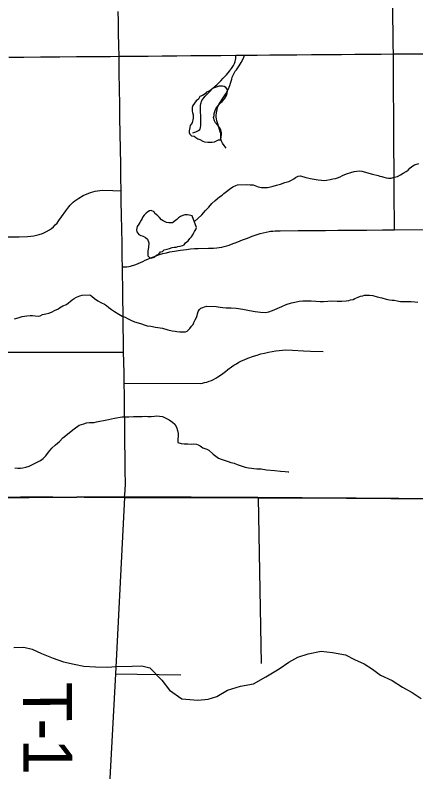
# Model space of a CAD drawing. Extents: x 0 to 34, y 0 to 22.
# Drawn here: x 3.526 to 3.992, y 15.034 to 15.914 of the extents above; entities that cross this region are included whole.
import ezdxf

# ---------------------------------------------------------------- set-up
doc = ezdxf.new("R2010")
doc.units = 0
for name, color, linetype in [('GM_X_City_Street', 7, 'Continuous'), ('GM_X_County_Road', 7, 'Continuous'), ('GM_X_County_Text', 7, 'Continuous'), ('GM_X_Minor_Lake', 7, 'Continuous'), ('GM_X_Minor_River', 7, 'Continuous'), ('GM_X_Township_Road', 7, 'Continuous'), ('GM_X_Township_Road_Text', 7, 'Continuous'), ('SH_Cut_Line', 7, 'Continuous')]:
    doc.layers.add(name, color=color, linetype=linetype)

msp = doc.modelspace()

# ---------------------------------------------------------------- linework, layer by layer
at = {"layer": 'GM_X_City_Street'}
msp.add_line((3.33353, 15.52258), (3.65196, 15.52258), dxfattribs=at)
for points in [[(3.65298, 15.35362), (3.65372, 15.36143), (3.65397, 15.36952), (3.6538, 15.38426), (3.65362, 15.39953), (3.6534, 15.41789), (3.65317, 15.43737), (3.65296, 15.45612), (3.65276, 15.47253), (3.6526, 15.48625), (3.6524, 15.49744), (3.65216, 15.51118), (3.65196, 15.52258), (3.65175, 15.53697), (3.65155, 15.55073), (3.6513, 15.56788), (3.65105, 15.58457), (3.65083, 15.59941), (3.65066, 15.61118), (3.65051, 15.6216), (3.65033, 15.63231), (3.65004, 15.64917), (3.64977, 15.66545), (3.6495, 15.68163), (3.64923, 15.69742), (3.64902, 15.70986), (3.64877, 15.72556), (3.64852, 15.74151), (3.64826, 15.75803), (3.64796, 15.7771), (3.64769, 15.79428), (3.64743, 15.81063), (3.64716, 15.8279), (3.64685, 15.84788), (3.64656, 15.86637), (3.64635, 15.87915), (3.64611, 15.89326), (3.64588, 15.90714), (3.64569, 15.91854)], [(3.96667, 15.66466), (3.96657, 15.68081), (3.96649, 15.69426), (3.96639, 15.71042), (3.9663, 15.72481), (3.96621, 15.73903), (3.9661, 15.75638), (3.96598, 15.77525), (3.96588, 15.79083), (3.9658, 15.80394), (3.96569, 15.82096), (3.96559, 15.83644), (3.96549, 15.85328), (3.96539, 15.86912), (3.96528, 15.87961), (3.9651, 15.8956), (3.96495, 15.90999), (3.96482, 15.92226)], [(3.73221, 15.77748), (3.73572, 15.77869), (3.73741, 15.77939), (3.73894, 15.78022), (3.74038, 15.78131), (3.74104, 15.78234), (3.74138, 15.78336), (3.74172, 15.7864), (3.7418, 15.79001), (3.74153, 15.79695), (3.74128, 15.8022), (3.74121, 15.80584), (3.74145, 15.80939), (3.74161, 15.81121), (3.74189, 15.81238), (3.74233, 15.8138), (3.74293, 15.81519), (3.7438, 15.81647), (3.74499, 15.81817), (3.74666, 15.82007), (3.74862, 15.82218), (3.75154, 15.82525), (3.75566, 15.82931), (3.76047, 15.83369), (3.76474, 15.8377), (3.76776, 15.84096), (3.76967, 15.84286), (3.7714, 15.84485), (3.77511, 15.8492), (3.77739, 15.85224), (3.77965, 15.85577), (3.7809, 15.85807), (3.78161, 15.8604), (3.78214, 15.86397), (3.78239, 15.86764)], [(3.77117, 15.75959), (3.76867, 15.76286), (3.76688, 15.76554), (3.76561, 15.76782), (3.76516, 15.76893), (3.76479, 15.7702), (3.76472, 15.77183), (3.76487, 15.77361), (3.76494, 15.77517), (3.76479, 15.77681), (3.76429, 15.77872), (3.76267, 15.78389), (3.76085, 15.78904), (3.76026, 15.79145), (3.75989, 15.7936), (3.75966, 15.79561), (3.75959, 15.79747), (3.75989, 15.80066), (3.76055, 15.80445), (3.76119, 15.80675), (3.76211, 15.80937), (3.76299, 15.81111), (3.76401, 15.81262), (3.76687, 15.81683), (3.77073, 15.82291), (3.77281, 15.82638), (3.77384, 15.8284), (3.77475, 15.8306), (3.77537, 15.83238), (3.77659, 15.83642), (3.7775, 15.83989), (3.77824, 15.84227), (3.77921, 15.84464), (3.78047, 15.84695), (3.78173, 15.84895), (3.78292, 15.85051), (3.78612, 15.85542), (3.78856, 15.85928), (3.7905, 15.8627), (3.79168, 15.86543), (3.79229, 15.8677)], [(3.51197, 15.65638), (3.53055, 15.65654), (3.54028, 15.65675), (3.54403, 15.65712), (3.54775, 15.65769), (3.55072, 15.65831), (3.55364, 15.65913), (3.55771, 15.66056), (3.56009, 15.66152), (3.56239, 15.66264), (3.56572, 15.66458), (3.5681, 15.66634), (3.57036, 15.66825), (3.5725, 15.67029), (3.57452, 15.67247), (3.57659, 15.67533), (3.5797, 15.67959), (3.58474, 15.68681), (3.58808, 15.69125), (3.58966, 15.69317), (3.59139, 15.69498), (3.59322, 15.69666), (3.59518, 15.69822), (3.59976, 15.70132), (3.60506, 15.70457), (3.60778, 15.70588), (3.61057, 15.70705), (3.61343, 15.70807), (3.61633, 15.70892), (3.61896, 15.7096), (3.62163, 15.71013), (3.62432, 15.71049), (3.62704, 15.71069), (3.63948, 15.71045), (3.64902, 15.70986)], [(3.65051, 15.6216), (3.65566, 15.62172), (3.6579, 15.62201), (3.6601, 15.62246), (3.66618, 15.62446), (3.67406, 15.62777), (3.67713, 15.62921), (3.68024, 15.63061), (3.68337, 15.63196), (3.68652, 15.63326), (3.68972, 15.63452), (3.69366, 15.63585), (3.69763, 15.63703), (3.70164, 15.63806), (3.70569, 15.63894), (3.71117, 15.63993), (3.71809, 15.641), (3.72502, 15.6419), (3.72955, 15.64242), (3.73411, 15.64278), (3.73869, 15.64298), (3.75046, 15.64328), (3.75648, 15.64342), (3.76019, 15.64366), (3.76313, 15.644), (3.76605, 15.64449), (3.76895, 15.64513), (3.77182, 15.64591), (3.77464, 15.64684), (3.77741, 15.6479), (3.78447, 15.65073), (3.79012, 15.65291), (3.79579, 15.65506), (3.80146, 15.65716), (3.80717, 15.65924), (3.81054, 15.66032), (3.81397, 15.66125), (3.81742, 15.66203), (3.8209, 15.66265), (3.82268, 15.66291), (3.82544, 15.66318), (3.82817, 15.66339), (3.83092, 15.66355), (3.83366, 15.66366), (3.85464, 15.66381), (3.8716, 15.66394), (3.88637, 15.66405), (3.90102, 15.66417), (3.91783, 15.66429), (3.93453, 15.66441), (3.95264, 15.66455), (3.96667, 15.66466), (4.14605, 15.66521)], [(3.76142, 15.49356), (3.76442, 15.49567), (3.76737, 15.49779), (3.77029, 15.49993), (3.77319, 15.50211), (3.77742, 15.50531), (3.78019, 15.50722), (3.78305, 15.50902), (3.786, 15.51067), (3.78902, 15.51218), (3.79212, 15.51357), (3.79634, 15.51532), (3.80276, 15.51768), (3.80709, 15.51908), (3.81144, 15.52031), (3.81581, 15.52141), (3.82019, 15.52238), (3.82459, 15.52323), (3.829, 15.52396), (3.83277, 15.52443), (3.83657, 15.52476), (3.84039, 15.52494), (3.84804, 15.52486), (3.86106, 15.52405), (3.86903, 15.52353), (3.88381, 15.52299)], [(3.6526, 15.48625), (3.74097, 15.48601), (3.74352, 15.48642), (3.74603, 15.48698), (3.74859, 15.48768), (3.75128, 15.48857), (3.7539, 15.48959), (3.75648, 15.49077), (3.75898, 15.49208), (3.76142, 15.49356)]]:
    msp.add_lwpolyline(points, dxfattribs=at)
at = {"layer": 'GM_X_County_Road'}
for points in [[(3.51867, 15.86544), (3.53611, 15.86556), (3.55529, 15.86571), (3.57798, 15.86587), (3.59734, 15.86601), (3.61069, 15.8661), (3.62377, 15.8662), (3.63684, 15.8663), (3.64656, 15.86637), (3.66286, 15.86652), (3.68029, 15.86668), (3.69671, 15.86684), (3.71368, 15.86699), (3.73001, 15.86715), (3.74872, 15.86732), (3.76505, 15.86748), (3.78239, 15.86764), (3.79229, 15.8677), (3.80729, 15.86783), (3.82178, 15.86794), (3.83671, 15.86807), (3.85304, 15.8682), (3.87019, 15.86834), (3.88762, 15.86848), (3.90515, 15.86863), (3.92073, 15.86876), (3.93485, 15.86888), (3.95126, 15.86901), (3.96539, 15.86912), (3.98495, 15.86927), (4.00386, 15.8694)], [(3.31965, 15.35275), (3.32685, 15.35266), (3.34348, 15.35257), (3.36284, 15.35247), (3.38921, 15.3528), (3.41758, 15.35316), (3.46127, 15.3537), (3.49575, 15.35397), (3.53219, 15.35424), (3.56973, 15.35405), (3.60612, 15.35385), (3.63761, 15.35369), (3.65298, 15.35362)], [(3.65298, 15.35362), (3.75893, 15.35326), (3.80845, 15.35317)], [(3.80845, 15.35317), (3.83837, 15.35291), (3.88316, 15.35318), (3.92208, 15.35305), (3.97186, 15.35278), (4.03204, 15.35224), (4.11628, 15.35259), (4.15233, 15.35257)]]:
    msp.add_lwpolyline(points, dxfattribs=at)
at = {"layer": 'GM_X_County_Text'}
msp.add_lwpolyline([(2.1, 20.9), (2.1, 15.35555), (2.59665, 15.35679), (2.84135, 15.35679), (3.01432, 15.35542), (3.32004, 15.35178), (3.65291, 15.35415), (3.80772, 15.35346), (4.11711, 15.35093), (4.18917, 15.35093), (4.32859, 15.35142), (4.54906, 15.3522), (4.6624, 15.35006), (5.06439, 15.33731), (5.42033, 15.33642), (5.45058, 15.33634), (5.47229, 15.33629), (5.50322, 15.33621), (5.57376, 15.33603), (5.61838, 15.33592), (5.91104, 15.33518), (6.05142, 15.33489), (6.61711, 15.32914), (8.9, 15.30473)], dxfattribs=at)
msp.add_lwpolyline([(2.1, 15.35555), (2.1, 14.1), (4.37869, 14.1), (4.37252, 14.1373), (4.36756, 14.15334), (4.41851, 14.2906), (4.47072, 14.50324), (4.00579, 14.50862), (4.00924, 14.86037), (4.00195, 15.17773), (4.11536, 15.18031), (4.11711, 15.35093), (3.80772, 15.35346), (3.65291, 15.35415), (3.32004, 15.35178), (3.01432, 15.35542), (2.84135, 15.35679), (2.59665, 15.35679)], close=True, dxfattribs=at)
at = {"layer": 'GM_X_Minor_Lake'}
for points in [[(3.73158, 15.80668), (3.73163, 15.8028), (3.73204, 15.8009), (3.73283, 15.79825), (3.73288, 15.79444), (3.73143, 15.7891), (3.7292, 15.78603), (3.72885, 15.78375), (3.72814, 15.77993), (3.72817, 15.77765), (3.72895, 15.77576), (3.73087, 15.77388), (3.73391, 15.77354), (3.73583, 15.77204), (3.73812, 15.77055), (3.74041, 15.76982), (3.74385, 15.76758), (3.74576, 15.76685), (3.74994, 15.76652), (3.75222, 15.76655), (3.75487, 15.76658), (3.75752, 15.767), (3.76205, 15.76934), (3.76395, 15.76936), (3.76542, 15.77242), (3.76576, 15.77547), (3.76573, 15.77775), (3.76493, 15.78078), (3.76377, 15.78305), (3.76183, 15.78569), (3.75875, 15.78907), (3.75759, 15.79134), (3.7564, 15.79513), (3.75713, 15.79742), (3.7571, 15.80008), (3.75819, 15.80351), (3.75892, 15.80543), (3.76117, 15.80812), (3.76266, 15.81004), (3.76453, 15.81234), (3.7664, 15.81389), (3.76902, 15.81696), (3.77163, 15.8208), (3.77235, 15.82347), (3.77269, 15.82614), (3.77229, 15.82803), (3.77075, 15.8303), (3.76883, 15.83141), (3.76693, 15.83177), (3.76503, 15.83175), (3.76314, 15.83172)], [(3.76314, 15.83172), (3.75596, 15.82935), (3.7522, 15.82626), (3.74843, 15.82469), (3.74655, 15.82276), (3.74354, 15.82082), (3.74052, 15.81964), (3.73904, 15.81658), (3.73641, 15.81465), (3.73231, 15.80927), (3.73158, 15.80698), (3.73158, 15.80668)], [(3.7314, 15.68093), (3.73017, 15.68146), (3.72599, 15.68217), (3.72296, 15.68213), (3.72069, 15.68134), (3.71805, 15.68016), (3.71579, 15.67861), (3.71392, 15.67669), (3.71203, 15.67552), (3.70865, 15.67282), (3.70448, 15.67277), (3.70182, 15.67311), (3.698, 15.67497), (3.69608, 15.67646), (3.69377, 15.67909), (3.69185, 15.68097), (3.68993, 15.68247), (3.68802, 15.68358), (3.68724, 15.68547), (3.68381, 15.68695), (3.68191, 15.68655), (3.68003, 15.68576), (3.67815, 15.68384), (3.67591, 15.68153), (3.67441, 15.67961), (3.6733, 15.67769), (3.67219, 15.67578), (3.6707, 15.6731), (3.66959, 15.67118), (3.66773, 15.66849), (3.66702, 15.66468), (3.66743, 15.6624), (3.66974, 15.65939), (3.67204, 15.6579), (3.67471, 15.65717), (3.67738, 15.65569), (3.67968, 15.65382), (3.68125, 15.64965), (3.68095, 15.64394), (3.68024, 15.64013), (3.67988, 15.63822), (3.67993, 15.63442), (3.68185, 15.63254), (3.68376, 15.63181), (3.68754, 15.633), (3.69017, 15.63531), (3.69281, 15.63649), (3.69467, 15.63917), (3.69694, 15.63958), (3.6992, 15.64151), (3.7026, 15.64232), (3.70525, 15.64311), (3.70827, 15.64391), (3.71054, 15.64432), (3.71282, 15.64435), (3.71509, 15.64514), (3.71774, 15.64555), (3.72038, 15.64635), (3.72227, 15.64713), (3.72376, 15.64943), (3.72676, 15.65175), (3.72901, 15.65444), (3.73088, 15.65637), (3.73274, 15.65943), (3.73421, 15.66287), (3.7357, 15.66518), (3.73643, 15.66747), (3.7314, 15.68093)]]:
    msp.add_lwpolyline(points, dxfattribs=at)
at = {"layer": 'GM_X_Minor_River'}
for points in [[(3.73397, 15.67404), (3.74269, 15.682), (3.74718, 15.687), (3.75092, 15.69085), (3.75428, 15.69508), (3.75841, 15.69893), (3.76328, 15.70318), (3.7663, 15.70512), (3.76855, 15.70705), (3.77155, 15.70937), (3.77494, 15.71207), (3.77869, 15.71478), (3.78247, 15.71635), (3.78436, 15.71714), (3.79422, 15.71726), (3.79916, 15.71695), (3.80257, 15.71699), (3.80829, 15.71478), (3.8121, 15.71369), (3.81628, 15.71374), (3.81931, 15.71378), (3.82121, 15.71418), (3.82574, 15.71538), (3.82952, 15.71657), (3.83406, 15.71777), (3.83935, 15.71974), (3.84389, 15.72094), (3.8469, 15.7225), (3.84954, 15.72405), (3.85179, 15.7256), (3.85481, 15.72716), (3.85746, 15.72758), (3.86356, 15.72537), (3.87117, 15.72395), (3.87801, 15.72289), (3.88181, 15.72256), (3.88486, 15.72184), (3.88751, 15.72226), (3.89205, 15.72307), (3.89508, 15.72387), (3.89811, 15.72429), (3.90038, 15.72508), (3.9034, 15.72626), (3.90641, 15.72782), (3.91094, 15.72978), (3.91585, 15.73136), (3.92001, 15.73256), (3.92304, 15.73297), (3.9257, 15.73339), (3.92874, 15.73267), (3.93293, 15.73158), (3.93674, 15.73049), (3.94131, 15.7294), (3.94778, 15.72797), (3.94968, 15.72723), (3.95197, 15.7265), (3.95425, 15.72577), (3.95692, 15.72504), (3.95958, 15.72469), (3.963, 15.72474), (3.9664, 15.72592), (3.97018, 15.72673), (3.97357, 15.72867), (3.97696, 15.73062), (3.98035, 15.73256), (3.98261, 15.73411), (3.98448, 15.73642), (3.98673, 15.73835), (3.99012, 15.74029), (3.99503, 15.74188)], [(3.56165, 15.56712), (3.56505, 15.56793), (3.56807, 15.5691), (3.57222, 15.57106), (3.57562, 15.57224), (3.5775, 15.57379), (3.58126, 15.57612), (3.58542, 15.57769), (3.58767, 15.57962), (3.58993, 15.58117), (3.59218, 15.5831), (3.59444, 15.58465), (3.59707, 15.58621), (3.60085, 15.58778), (3.60387, 15.58858), (3.61259, 15.58907), (3.61489, 15.58758), (3.61796, 15.58495), (3.62179, 15.58196), (3.62638, 15.57974), (3.62981, 15.57826), (3.63211, 15.57677), (3.63479, 15.57452), (3.63786, 15.5719), (3.64131, 15.56966), (3.64628, 15.56668), (3.6501, 15.56444), (3.65354, 15.56297), (3.65659, 15.56149), (3.66041, 15.55963), (3.66461, 15.55779), (3.6688, 15.55632), (3.67261, 15.55522), (3.67566, 15.55412), (3.67947, 15.55303), (3.68365, 15.5527), (3.68898, 15.55163), (3.69697, 15.55021), (3.70344, 15.54839), (3.70839, 15.54731), (3.71181, 15.54697), (3.71371, 15.54662), (3.71714, 15.5459), (3.72017, 15.54594), (3.72207, 15.54597), (3.72396, 15.54599), (3.72585, 15.54677), (3.72885, 15.54986), (3.73071, 15.55254), (3.73258, 15.55447), (3.73369, 15.55676), (3.73517, 15.55982), (3.73665, 15.56288), (3.73738, 15.56518), (3.73773, 15.56708), (3.73846, 15.56975), (3.73994, 15.57205), (3.74182, 15.5736), (3.74409, 15.57439), (3.74597, 15.57517), (3.74862, 15.57597), (3.75963, 15.57535), (3.7642, 15.57465), (3.76724, 15.5743), (3.77103, 15.57397), (3.77673, 15.57404), (3.7828, 15.57374), (3.79041, 15.57232), (3.79802, 15.57089), (3.80486, 15.56984), (3.81095, 15.56878), (3.81664, 15.56847), (3.82081, 15.56928), (3.82496, 15.57086), (3.83025, 15.5732), (3.83591, 15.57556), (3.84081, 15.5779), (3.84686, 15.57988), (3.85102, 15.58069), (3.85594, 15.58152), (3.86011, 15.58195), (3.86428, 15.582), (3.86998, 15.58208), (3.87529, 15.58176), (3.88023, 15.58145), (3.8844, 15.5815), (3.88934, 15.58156), (3.89351, 15.582), (3.89996, 15.5817), (3.90565, 15.58177), (3.91058, 15.58221), (3.91361, 15.58263), (3.9155, 15.58342), (3.91853, 15.58383), (3.92079, 15.58462), (3.92457, 15.58619), (3.92721, 15.58737), (3.92986, 15.58778), (3.93175, 15.58857), (3.93517, 15.58861), (3.93782, 15.58865)], [(3.93782, 15.58865), (3.94162, 15.58831), (3.94657, 15.58685), (3.9519, 15.5854), (3.95685, 15.58394), (3.96104, 15.58324), (3.96408, 15.58289), (3.96636, 15.58292), (3.96978, 15.58221), (3.97358, 15.58149), (3.98611, 15.58127), (3.99029, 15.58095), (3.99371, 15.58061)], [(3.52529, 15.56133), (3.52946, 15.56215), (3.53399, 15.56373), (3.53929, 15.56455), (3.54346, 15.56499), (3.54612, 15.56502), (3.54916, 15.56468), (3.55258, 15.56434), (3.55485, 15.56475), (3.55748, 15.56631), (3.56165, 15.56712)], [(3.52565, 15.38792), (3.52907, 15.38758), (3.5321, 15.38762), (3.53475, 15.38803), (3.53816, 15.38884), (3.54232, 15.39003), (3.5476, 15.39276), (3.55514, 15.39628), (3.55853, 15.39861), (3.56152, 15.40206), (3.5645, 15.40629), (3.56861, 15.4109), (3.57274, 15.41476), (3.57724, 15.41862), (3.58136, 15.42286), (3.5945, 15.43329), (3.60014, 15.43754), (3.60581, 15.43914), (3.60883, 15.44032), (3.61224, 15.44074), (3.6149, 15.44078), (3.61756, 15.44081), (3.62059, 15.44123), (3.62437, 15.44204), (3.62853, 15.44285), (3.63421, 15.44406), (3.6414, 15.44568), (3.65011, 15.44731), (3.65807, 15.44741), (3.66339, 15.44748), (3.66908, 15.44755), (3.67363, 15.44761), (3.67704, 15.44803), (3.68008, 15.44769), (3.68388, 15.44774), (3.68766, 15.44817), (3.6907, 15.44821), (3.69374, 15.44786), (3.69716, 15.44753), (3.70022, 15.44605), (3.7048, 15.44382), (3.70863, 15.44121), (3.71132, 15.43858), (3.71326, 15.43518), (3.71445, 15.4314), (3.71525, 15.42798), (3.71529, 15.42456), (3.71496, 15.42113), (3.71501, 15.41733), (3.71882, 15.41624), (3.72224, 15.4159), (3.72641, 15.41596), (3.73097, 15.41563), (3.73325, 15.41566)], [(3.73325, 15.41566), (3.73667, 15.41533), (3.73857, 15.41459), (3.74086, 15.41348), (3.74393, 15.41123), (3.7485, 15.40977), (3.7508, 15.40828), (3.75617, 15.40378), (3.75923, 15.40154), (3.7623, 15.3993), (3.76535, 15.39782), (3.76878, 15.39672), (3.77336, 15.39526), (3.77641, 15.39415), (3.78021, 15.39344), (3.78403, 15.39197), (3.7886, 15.39012), (3.79318, 15.38866), (3.79698, 15.38795), (3.8004, 15.38761), (3.80344, 15.38727), (3.80686, 15.38693), (3.8118, 15.38662), (3.81788, 15.38555), (3.82776, 15.38492), (3.83422, 15.38424), (3.83954, 15.38355), (3.84334, 15.38322), (3.8441, 15.38322)], [(3.52419, 15.17899), (3.53593, 15.1795), (3.54582, 15.17695), (3.55648, 15.17213), (3.57019, 15.16659), (3.58198, 15.16254), (3.59452, 15.15964), (3.60553, 15.15749), (3.61919, 15.1565), (3.63322, 15.15628), (3.64344, 15.15678), (3.66201, 15.15737), (3.673, 15.15787), (3.6825, 15.15532), (3.6963, 15.14104), (3.70515, 15.12936), (3.71966, 15.11926), (3.73825, 15.11795), (3.75036, 15.11885), (3.76018, 15.122), (3.77261, 15.12936), (3.78772, 15.13409), (3.80285, 15.13692), (3.81716, 15.14506), (3.8326, 15.15435), (3.84388, 15.16208), (3.85443, 15.1679), (3.86652, 15.17184), (3.88165, 15.17467), (3.89455, 15.17329), (3.90974, 15.17042), (3.92041, 15.16522), (3.93146, 15.16003), (3.941, 15.15368), (3.95055, 15.14695), (3.96389, 15.14064), (3.9761, 15.1328), (3.98716, 15.12684), (3.99785, 15.11975)]]:
    msp.add_lwpolyline(points, dxfattribs=at)
at = {"layer": 'GM_X_Township_Road'}
for p, q in [((3.80845, 15.35317), (3.81162, 15.16054)), ((3.64229, 15.14856), (3.71854, 15.14718))]:
    msp.add_line(p, q, dxfattribs=at)
for points in [[(3.31965, 15.35275), (3.32685, 15.35266), (3.34348, 15.35257), (3.36284, 15.35247), (3.38921, 15.3528), (3.41758, 15.35316), (3.46127, 15.3537), (3.49575, 15.35397), (3.53219, 15.35424), (3.56973, 15.35405), (3.60612, 15.35385), (3.63761, 15.35369), (3.65298, 15.35362)], [(3.65298, 15.35362), (3.64229, 15.14856), (3.63457, 15.0053), (3.62797, 14.86389)], [(3.65298, 15.35362), (3.75893, 15.35326), (3.80845, 15.35317)], [(3.80845, 15.35317), (3.83837, 15.35291), (3.88316, 15.35318), (3.92208, 15.35305), (3.97186, 15.35278), (4.03204, 15.35224), (4.11628, 15.35259), (4.15233, 15.35257)]]:
    msp.add_lwpolyline(points, dxfattribs=at)
at = {"layer": 'SH_Cut_Line'}
for points in [[(2.1, 20.9), (2.1, 15.35555), (2.59665, 15.35679), (2.84135, 15.35679), (3.01432, 15.35542), (3.32004, 15.35178), (3.65291, 15.35415), (3.80772, 15.35346), (4.11711, 15.35093), (4.18917, 15.35093), (4.32859, 15.35142), (4.54906, 15.3522), (4.6624, 15.35006), (5.06439, 15.33731), (5.42033, 15.33642), (5.45058, 15.33634), (5.47229, 15.33629), (5.50322, 15.33621), (5.57376, 15.33603), (5.61838, 15.33592), (5.91104, 15.33518), (6.05142, 15.33489), (6.61711, 15.32914), (8.9, 15.30473)], [(8.9, 15.30473), (6.61711, 15.32914), (6.05142, 15.33489), (5.91104, 15.33518), (5.61838, 15.33592), (5.57376, 15.33603), (5.50322, 15.33621), (5.47229, 15.33629), (5.45058, 15.33634), (5.42033, 15.33642), (5.06439, 15.33731), (4.6624, 15.35006), (4.54906, 15.3522), (4.32859, 15.35142), (4.18917, 15.35093), (4.11711, 15.35093), (3.80772, 15.35346), (3.65291, 15.35415), (3.32004, 15.35178), (3.01432, 15.35542), (2.84135, 15.35679), (2.59665, 15.35679), (2.1, 15.35555)]]:
    msp.add_lwpolyline(points, dxfattribs=at)

# ---------------------------------------------------------------- texts
at = {"layer": 'GM_X_Township_Road_Text'}
for s, rotation, p in [('T', 270.35143, (3.535, 15.13889)), ('-', 270.31225, (3.53526, 15.0964)), ('1', 270.14052, (3.53539, 15.07312))]:
    msp.add_text(s, height=0.05682, rotation=rotation, dxfattribs=at).set_placement(p)

doc.saveas('drawing.dxf')
